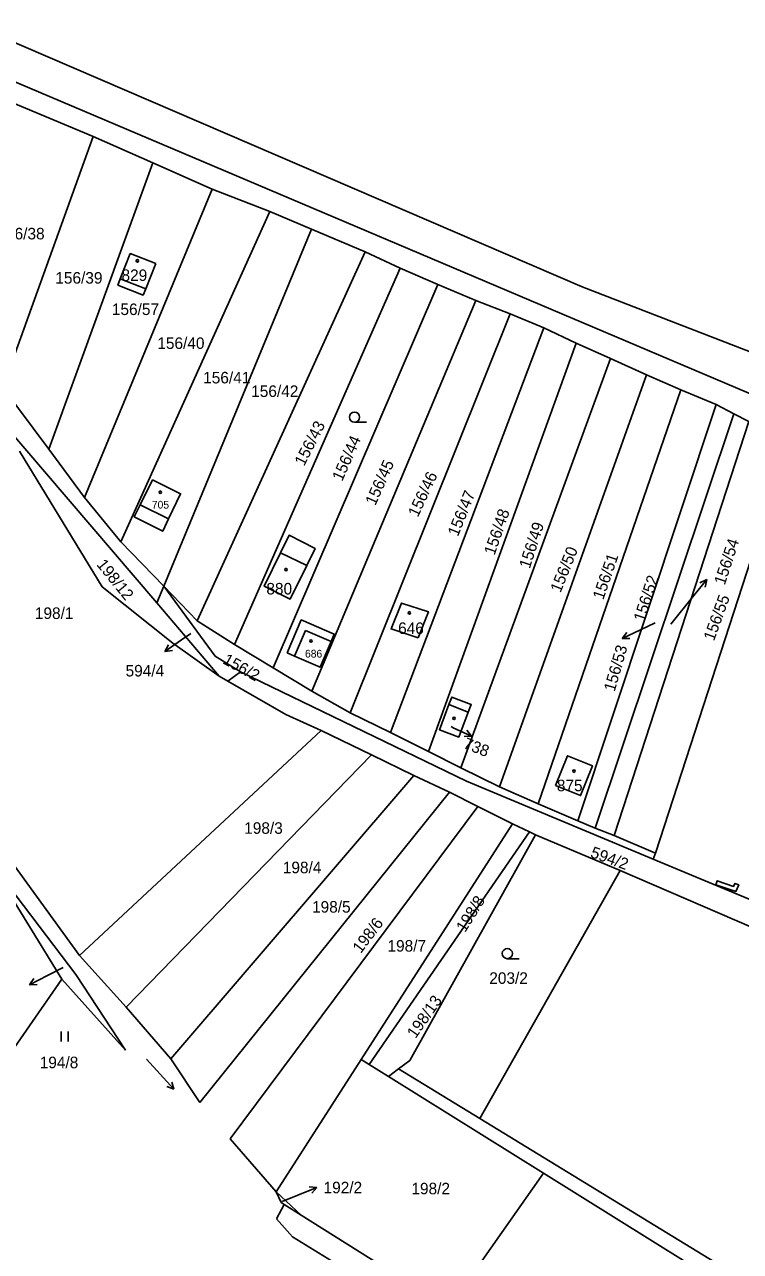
# Model space of a CAD drawing. Extents: x -783948 to -781889, y -1005870 to -1004430.
# Drawn here: x -782787.9 to -782682.3, y -1005271.1 to -1005090.2 of the extents above; entities that cross this region are included whole.
import ezdxf

# ---------------------------------------------------------------- set-up
doc = ezdxf.new("R2010")
doc.units = 0
for name, color, linetype in [('Vrstva 1', 7, 'Continuous'), ('Vrstva 13', 7, 'Continuous'), ('Vrstva 2', 7, 'Continuous'), ('Vrstva 3', 7, 'Continuous'), ('Vrstva 4', 7, 'Continuous'), ('Vrstva 5', 7, 'Continuous'), ('Vrstva 6', 7, 'Continuous'), ('Vrstva 7', 7, 'Continuous')]:
    doc.layers.add(name, color=color, linetype=linetype)

msp = doc.modelspace()

# ---------------------------------------------------------------- linework, layer by layer
at = {"layer": 'Vrstva 1'}
for p, q in [((-782789.82, -1005101.7), (-782777.73, -1005106.76)), ((-782791.04, -1005143.73), (-782777.73, -1005106.76)), ((-782777.73, -1005106.76), (-782768.96, -1005110.62)), ((-782784.29, -1005152.86), (-782768.96, -1005110.62)), ((-782768.96, -1005110.62), (-782760.2, -1005114.49)), ((-782760.2, -1005114.49), (-782779.04, -1005159.97)), ((-782760.2, -1005114.49), (-782751.71, -1005117.8)), ((-782773.67, -1005166.48), (-782751.71, -1005117.8)), ((-782751.71, -1005117.8), (-782745.53, -1005120.4)), ((-782767.34, -1005173.02), (-782745.53, -1005120.4)), ((-782745.53, -1005120.4), (-782737.65, -1005123.73)), ((-782762.4, -1005178.13), (-782737.65, -1005123.73)), ((-782737.65, -1005123.73), (-782732.46, -1005126.16)), ((-782756.88, -1005181.64), (-782732.46, -1005126.16)), ((-782732.46, -1005126.16), (-782726.9, -1005128.54)), ((-782751.2, -1005185.09), (-782726.9, -1005128.54)), ((-782726.9, -1005128.54), (-782721.33, -1005130.91)), ((-782745.52, -1005188.54), (-782721.33, -1005130.91)), ((-782721.33, -1005130.91), (-782716.26, -1005132.9)), ((-782739.86, -1005191.7), (-782716.26, -1005132.9)), ((-782716.26, -1005132.9), (-782711.31, -1005134.96)), ((-782733.9, -1005194.59), (-782711.31, -1005134.96)), ((-782711.31, -1005134.96), (-782706.52, -1005137.22)), ((-782728.29, -1005197.41), (-782706.52, -1005137.22)), ((-782706.52, -1005137.22), (-782701.48, -1005139.47)), ((-782723.51, -1005199.83), (-782701.48, -1005139.47)), ((-782701.48, -1005139.47), (-782696.15, -1005141.86)), ((-782717.85, -1005202.61), (-782696.15, -1005141.86)), ((-782696.15, -1005141.86), (-782691.12, -1005144.07)), ((-782784.29, -1005152.86), (-782791.04, -1005143.73)), ((-782712.12, -1005205.12), (-782691.12, -1005144.07)), ((-782691.12, -1005144.07), (-782685.9, -1005146.26)), ((-782706.3, -1005207.64), (-782685.9, -1005146.26)), ((-782685.9, -1005146.26), (-782683.3, -1005147.64)), ((-782703.74, -1005208.72), (-782683.3, -1005147.64)), ((-782683.3, -1005147.64), (-782681.06, -1005148.77)), ((-782791.29, -1005148.67), (-782768.37, -1005175.51)), ((-782700.91, -1005209.8), (-782681.06, -1005148.77)), ((-782675.11, -1005151.66), (-782694.84, -1005212.38)), ((-782779.04, -1005159.97), (-782784.29, -1005152.86)), ((-782773.67, -1005166.48), (-782779.04, -1005159.97)), ((-782767.34, -1005173.02), (-782773.67, -1005166.48)), ((-782768.37, -1005175.51), (-782767.34, -1005173.02)), ((-782762.4, -1005178.13), (-782767.34, -1005173.02)), ((-782759.14, -1005186.33), (-782768.37, -1005175.51)), ((-782756.88, -1005181.64), (-782762.4, -1005178.13)), ((-782751.2, -1005185.09), (-782756.88, -1005181.64)), ((-782757.9, -1005187.04), (-782759.14, -1005186.33)), ((-782756.03, -1005185.68), (-782757.9, -1005187.04)), ((-782745.52, -1005188.54), (-782751.2, -1005185.09)), ((-782739.86, -1005191.7), (-782745.52, -1005188.54)), ((-782733.9, -1005194.59), (-782739.86, -1005191.7)), ((-782779.76, -1005227.49), (-782744.13, -1005194.33)), ((-782736.72, -1005197.91), (-782744.13, -1005194.33)), ((-782728.29, -1005197.41), (-782733.9, -1005194.59)), ((-782772.89, -1005235.12), (-782736.72, -1005197.91)), ((-782730.48, -1005200.93), (-782736.72, -1005197.91)), ((-782723.51, -1005199.83), (-782728.29, -1005197.41)), ((-782717.85, -1005202.61), (-782723.51, -1005199.83)), ((-782766.27, -1005242.73), (-782730.48, -1005200.93)), ((-782725.2, -1005203.4), (-782730.48, -1005200.93)), ((-782712.12, -1005205.12), (-782717.85, -1005202.61)), ((-782762.01, -1005249.15), (-782725.2, -1005203.4)), ((-782721.01, -1005205.51), (-782725.2, -1005203.4)), ((-782757.52, -1005254.51), (-782721.01, -1005205.51)), ((-782715.94, -1005208.07), (-782721.01, -1005205.51)), ((-782706.3, -1005207.64), (-782712.12, -1005205.12)), ((-782738.24, -1005242.82), (-782715.94, -1005208.07)), ((-782713.4, -1005209.28), (-782715.94, -1005208.07)), ((-782703.74, -1005208.72), (-782706.3, -1005207.64)), ((-782737.03, -1005243.57), (-782713.4, -1005209.28)), ((-782713.4, -1005209.28), (-782712.51, -1005209.7)), ((-782700.06, -1005214.94), (-782712.51, -1005209.7)), ((-782700.91, -1005209.8), (-782703.74, -1005208.72)), ((-782694.84, -1005212.38), (-782700.91, -1005209.8)), ((-782791.38, -1005211.44), (-782779.76, -1005227.49)), ((-782793.47, -1005212.99), (-782782.38, -1005230.97)), ((-782695.19, -1005213.28), (-782694.84, -1005212.38)), ((-782695.19, -1005213.28), (-782681.01, -1005219.18)), ((-782700.06, -1005214.94), (-782720.73, -1005251.53)), ((-782652.68, -1005235.38), (-782700.06, -1005214.94)), ((-782779.76, -1005227.49), (-782772.89, -1005235.12)), ((-782782.38, -1005230.97), (-782791.93, -1005244.74)), ((-782782.38, -1005230.97), (-782772.95, -1005241.45)), ((-782772.89, -1005235.12), (-782766.27, -1005242.73)), ((-782766.27, -1005242.73), (-782762.01, -1005249.15)), ((-782738.24, -1005242.82), (-782750.75, -1005262.33)), ((-782737.03, -1005243.57), (-782738.24, -1005242.82)), ((-782734.2, -1005245.34), (-782737.03, -1005243.57)), ((-782732.71, -1005244.21), (-782734.2, -1005245.34)), ((-782720.73, -1005251.53), (-782732.71, -1005244.21)), ((-782711.35, -1005259.59), (-782734.2, -1005245.34)), ((-782757.52, -1005254.51), (-782750.75, -1005262.33)), ((-782725.32, -1005279.41), (-782711.35, -1005259.59)), ((-782711.35, -1005259.59), (-782690.29, -1005272.71)), ((-782750.75, -1005262.33), (-782747.06, -1005265.77)), ((-782749.56, -1005264.2), (-782750.69, -1005266.33)), ((-782747.06, -1005265.77), (-782749.56, -1005264.2)), ((-782725.32, -1005279.41), (-782747.06, -1005265.77)), ((-782748.34, -1005268.96), (-782750.69, -1005266.33)), ((-782719.96, -1005286.37), (-782748.34, -1005268.96))]:
    msp.add_line(p, q, dxfattribs=at)
for points in [[(-782603.34, -1005170.09), (-782670.21, -1005142.63), (-782705.63, -1005128.88), (-782803.2, -1005086.94), (-782810.41, -1005084.95), (-782850.5, -1005065.89)], [(-782768.51, -1005125.46), (-782769.99, -1005129.21), (-782770.37, -1005130.12), (-782774.09, -1005128.65), (-782773.75, -1005127.74), (-782772.26, -1005123.99), (-782768.51, -1005125.46)], [(-782759.14, -1005186.33), (-782765.98, -1005181.44), (-782776.41, -1005173.12), (-782788.58, -1005153.12)], [(-782770.79, -1005161.04), (-782768.99, -1005157.38), (-782764.84, -1005159.42), (-782766.61, -1005163.11), (-782767.49, -1005164.94), (-782771.67, -1005162.83), (-782770.79, -1005161.04)], [(-782746.26, -1005169.98), (-782748.71, -1005174.95), (-782752.51, -1005173.06), (-782750.1, -1005168.12), (-782748.85, -1005165.53), (-782745.03, -1005167.49), (-782746.26, -1005169.98)], [(-782767.34, -1005173.02), (-782759.73, -1005183.36), (-782756.03, -1005185.68)], [(-782729.83, -1005180.67), (-782733.81, -1005179.34), (-782732.28, -1005175.53), (-782728.32, -1005176.8), (-782729.83, -1005180.67)], [(-782749.16, -1005182.89), (-782747.06, -1005178.02), (-782742.19, -1005180.11), (-782742.67, -1005181.21), (-782744.29, -1005184.98), (-782748.05, -1005183.36), (-782749.16, -1005182.89)], [(-782756.03, -1005185.68), (-782722.72, -1005201.8), (-782695.19, -1005213.28)], [(-782744.13, -1005194.33), (-782749.34, -1005191.97), (-782757.9, -1005187.04)], [(-782725.28, -1005190.5), (-782724.86, -1005189.39), (-782722, -1005190.48), (-782722.43, -1005191.6), (-782723.84, -1005195.29), (-782726.68, -1005194.21), (-782725.28, -1005190.5)], [(-782709.6, -1005202.44), (-782707.83, -1005198.03), (-782704.13, -1005199.53), (-782705.87, -1005203.91), (-782709.6, -1005202.44)], [(-782712.51, -1005209.7), (-782731.04, -1005242.95), (-782732.71, -1005244.21)], [(-782793.47, -1005212.99), (-782780.29, -1005230.31), (-782772.95, -1005241.45)], [(-782602.36, -1005293.1), (-782612, -1005293.7), (-782623.5, -1005291.18), (-782649.46, -1005291.34), (-782662.07, -1005287.39), (-782720.73, -1005251.53)], [(-782749.56, -1005264.2), (-782750.04, -1005263.9), (-782750.75, -1005262.33)]]:
    msp.add_lwpolyline(points, dxfattribs=at)
at = {"layer": 'Vrstva 13'}
msp.add_lwpolyline([(-782685.92, -1005217.05), (-782682.97, -1005218.04), (-782682.57, -1005217.09), (-782683.12, -1005216.86), (-782683.31, -1005217.3), (-782685.73, -1005216.48)], close=True, dxfattribs=at)
at = {"layer": 'Vrstva 3'}
for p, q in [((-782739.21, -1005148.87), (-782737.46, -1005148.87)), ((-782716.68, -1005227.96), (-782714.93, -1005227.96)), ((-782782.44, -1005240.18), (-782782.44, -1005238.68)), ((-782781.44, -1005240.18), (-782781.44, -1005238.68)), ((-782769.86, -1005242.75), (-782765.85, -1005247.21)), ((-782765.85, -1005247.21), (-782766.87, -1005246.82)), ((-782765.85, -1005247.21), (-782766.13, -1005246.15))]:
    msp.add_line(p, q, dxfattribs=at)
for centre in [(-782739.21, -1005148.12), (-782716.68, -1005227.21)]:
    msp.add_circle(centre, 0.75, dxfattribs=at)
at = {"layer": 'Vrstva 4'}
for p, q in [((-782773.75, -1005127.74), (-782769.99, -1005129.21)), ((-782770.79, -1005161.04), (-782766.61, -1005163.11)), ((-782750.1, -1005168.12), (-782746.26, -1005169.98)), ((-782748.05, -1005183.36), (-782746.43, -1005179.59)), ((-782742.67, -1005181.21), (-782746.43, -1005179.59)), ((-782725.28, -1005190.5), (-782722.43, -1005191.6))]:
    msp.add_line(p, q, dxfattribs=at)
at = {"layer": 'Vrstva 5'}
for centre in [(-782771.22, -1005125.07), (-782767.85, -1005159.18), (-782749.29, -1005170.58), (-782731.11, -1005176.97), (-782745.64, -1005181.11), (-782724.52, -1005192.54), (-782706.85, -1005200.31)]:
    msp.add_circle(centre, 0.175, dxfattribs=at)
at = {"layer": 'Vrstva 6'}
msp.add_line((-782841.72, -1005076.44), (-782641.6, -1005161.34), dxfattribs=at)
at = {"layer": 'Vrstva 7'}
for p, q in [((-782689.17, -1005174.4), (-782687.28, -1005172.07)), ((-782687.28, -1005172.07), (-782688.3, -1005172.53)), ((-782687.28, -1005172.07), (-782687.52, -1005173.16)), ((-782692.57, -1005178.64), (-782689.17, -1005174.4)), ((-782694.87, -1005178.44), (-782697.04, -1005179.46)), ((-782763.35, -1005180.03), (-782764.71, -1005180.97)), ((-782697.04, -1005179.46), (-782699.76, -1005180.73)), ((-782699.76, -1005180.73), (-782699.06, -1005179.85)), ((-782699.76, -1005180.73), (-782698.64, -1005180.76)), ((-782764.71, -1005180.97), (-782767.17, -1005182.69)), ((-782767.17, -1005182.69), (-782766.64, -1005181.71)), ((-782767.17, -1005182.69), (-782766.06, -1005182.53)), ((-782724.98, -1005193.75), (-782724.66, -1005193.9)), ((-782724.66, -1005193.9), (-782721.94, -1005195.17)), ((-782721.94, -1005195.17), (-782723.06, -1005195.2)), ((-782721.94, -1005195.17), (-782722.64, -1005194.29)), ((-782782.18, -1005229.27), (-782784.46, -1005230.43)), ((-782784.46, -1005230.43), (-782787.13, -1005231.79)), ((-782787.13, -1005231.79), (-782786.47, -1005230.89)), ((-782787.13, -1005231.79), (-782786.01, -1005231.78)), ((-782747.56, -1005262.82), (-782744.78, -1005261.7)), ((-782744.78, -1005261.7), (-782745.89, -1005261.61)), ((-782744.78, -1005261.7), (-782745.52, -1005262.54)), ((-782749.89, -1005263.75), (-782747.56, -1005262.82))]:
    msp.add_line(p, q, dxfattribs=at)

# ---------------------------------------------------------------- texts
at = {"layer": 'Vrstva 2'}
for s, height, p in [('156/38', 1.7, (-782791.85, -1005121.91)), ('156/39', 1.7, (-782783.32, -1005128.43)), ('829', 1.7, (-782773.56, -1005128.04)), ('156/57', 1.7, (-782774.98, -1005133.06)), ('156/40', 1.7, (-782768.28, -1005138.06)), ('156/41', 1.7, (-782761.52, -1005143.14)), ('156/42', 1.7, (-782754.44, -1005145.14)), ('705', 1.139, (-782769.09, -1005161.6)), ('880', 1.7, (-782752.2, -1005174.26)), ('198/1', 1.7, (-782786.33, -1005177.87)), ('646', 1.7, (-782732.78, -1005180.08)), ('686', 1.14, (-782746.51, -1005183.56)), ('594/4', 1.7, (-782772.96, -1005186.35)), ('875', 1.7, (-782709.38, -1005203.27)), ('198/3', 1.7, (-782755.47, -1005209.55)), ('198/4', 1.7, (-782749.78, -1005215.36)), ('198/5', 1.7, (-782745.47, -1005221.17)), ('198/7', 1.7, (-782734.35, -1005226.92)), ('203/2', 1.7, (-782719.34, -1005231.67)), ('194/8', 1.7, (-782785.62, -1005244.11)), ('192/2', 1.7, (-782743.77, -1005262.55)), ('198/2', 1.7, (-782730.82, -1005262.7))]:
    msp.add_text(s, height=height, dxfattribs=at).set_placement(p)
for s, rotation, p in [('156/43', 63, (-782746.64, -1005155.44)), ('156/44', 66, (-782741.04, -1005157.68)), ('156/45', 66, (-782736.15, -1005161.26)), ('156/46', 65, (-782729.87, -1005162.97)), ('156/47', 68, (-782723.97, -1005165.82)), ('156/48', 71, (-782718.57, -1005168.58)), ('156/49', 72, (-782713.38, -1005170.55)), ('156/54', 72, (-782684.63, -1005172.98)), ('156/50', 68, (-782708.84, -1005174.1)), ('198/12', 309, (-782777.32, -1005169.88)), ('156/51', 71, (-782702.54, -1005175.15)), ('156/52', 72, (-782696.5, -1005178.39)), ('156/55', 70, (-782686.22, -1005181.22)), ('156/53', 74, (-782700.86, -1005188.69)), ('156/2', 331, (-782758.76, -1005184.36)), ('738', 339, (-782723.3, -1005196.89)), ('594/2', 340, (-782704.55, -1005212.96)), ('198/8', 58, (-782722.91, -1005224.18)), ('198/6', 53, (-782738.29, -1005227.28)), ('198/13', 55, (-782730.21, -1005239.82))]:
    msp.add_text(s, height=1.7, rotation=rotation, dxfattribs=at).set_placement(p)

doc.saveas('drawing.dxf')
